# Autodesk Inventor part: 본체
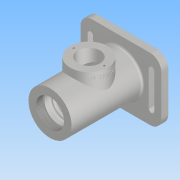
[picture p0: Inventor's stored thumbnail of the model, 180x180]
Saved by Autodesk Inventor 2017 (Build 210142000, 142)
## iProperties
Part Number: 본체
Material: 알루미늄 6061
Document SubType Name: Modeling
Designer: user
Density: 2.7 g/cm^3
Appearance: 알루미늄 - 평지
Mass: 734.635 g
Surface Area: 649.396 cm^2
Volume: 272.087 cm^3
Author: user
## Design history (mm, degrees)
sketch "스케치1"
  geometry: L1 (-58, -45)-(58, -45); L2 (58, -45)-(58, 45); L3 (58, 45)-(-58, 45); L4 (-58, 45)-(-58, -45); L5 (-58, -45)-(58, 45); L6 (58, -45)-(-58, 45); 1 further point
  constraints: 12 end point, 2 midpoint, 2 parallel, 1 horizontal, 1 perpendicular
  dimensions: "d0" = 116 distance of L3.end L2.end; "d1" = 90 distance of L2.end L1.end
extrude "돌출1" new body sketch "스케치1" distance "d2" = 10; taper "d3" = 0 deg
sketch "스케치2"
  geometry: C1 r 35 at (0, 0); 1 further point
  constraints: 1 centre point, 1 coincident
  dimensions: "d4" = 70 diameter of C1
extrude "돌출2" join sketch "스케치2" distance "d5" = 3; taper "d6" = 0 deg
sketch "스케치3"
  geometry: L1 (31, 112)-(0, 112); L2 (0, 112)-(0, 10); L3 (31, -3)-(31, 112); L4 (45, 10)-(-45, 10) reference; L5 (0, 103)-(24, 103); L6 (24, 103)-(24, 100); L7 (24, 100)-(20, 100); L8 (20, 100)-(20, 91); L9 (20, 91)-(17.5, 91); L10 (17.5, 91)-(17.5, 87.75); L11 (17.5, 87.75)-(18.5, 87.75); L12 (18.5, 87.75)-(18.5, 86); L13 (18.5, 86)-(17.5, 86); L14 (17.5, 86)-(17.5, 75); L15 (17.5, 75)-(26, 75); L16 (26, 75)-(26, 37); L17 (26, 37)-(17.5, 37); L18 (17.5, 37)-(17.5, 26); L19 (17.5, 26)-(16, 26); L20 (16, 26)-(16, 21); L21 (16, 21)-(10, 21); L22 (10, 21)-(10, 18.3); L23 (10, 18.3)-(12.5, 18.3); L24 (12.5, 18.3)-(12.5, 11); L25 (12.5, 11)-(17.5, 11); L26 (0, 112)-(0, 103); L27 (-35, -3)-(35, -3) reference; L28 (17.5, 11)-(22, -3); L29 (22, -3)-(31, -3); L30 (0, 103)-(0, -3); L31 (22, -3)-(0, -3); 3 further points
  constraints: 58 end point, 20 perpendicular, 8 point on line, 3 horizontal, 2 collinear, 2 midpoint, 1 coincident, 1 parallel, 1 vertical alignment
  dimensions: "d8" = 62 diameter of L3 L2; "d9" = 3 distance between parallel lines of L5 L7; "d10" = 12 distance between parallel lines of L7 L1; "d11" = 48 diameter of L6 L2; "d12" = 40 diameter of L8 L2; "d13" = 35 diameter of L10 L2; "d14" = 37 diameter of L12 L2; "d16" = 21 distance between parallel lines of L1 L9; "d21" = 91 distance between parallel lines of L1 L21; "d25" = 35 diameter of L14 L2; "d26" = 52 diameter of L16 L2; "d27" = 32 diameter of L20 L2; "d28" = 25 diameter of L24 L2; "d29" = 20 diameter of L22 L2; "d47" = 3.25 distance of L9.end L10.end; "d48" = 1.75 distance of L11.end L12.end; "d49" = 11 distance of L13.end L14.end; "d50" = 38 distance of L15.end L16.end; "d51" = 11 distance of L17.end L18.end; "d52" = 115 distance from line of L27 L1.start; "d53" = 44 diameter of L28.end L2; "d54" = 14 vertical distance of L28.end L25.end; "d55" = 7.3 distance of L23.end L24.end
revolve "회전1" stored, may be unused: angle "d31" = 90 deg
sketch "스케치4"
  geometry: C1 r 31 at (0, 0) reference; 1 further point
  constraints: 1 coincident
hole "구멍1" sketch "스케치4" at (0, 0) diameter "d32" = 40.376; stored, may be unused: countersink angle "d36" = 90 deg, drill point angle "d38" = 0 deg; dims "d33" = 9, "d34" = 4, "d35" = 2, "d37" = 9
revolve "회전2" stored, may be unused: angle "d56" = 90 deg
sketch "스케치7"
  geometry: L1 (44, 29)-(44, -29); L2 (40, 25)-(40, -25); L3 (48, -25)-(48, 25); C1 r 31 at (0, 0) reference; A1 r 4 centre (44, 25) between (48, 25) and (40, 25); A2 r 4 centre (44, -25) between (40, -25) and (48, -25); 1 further point
  constraints: 8 end point, 6 point on circle, 4 tangent, 2 centre point, 2 point on line, 1 horizontal alignment, 1 midpoint, 1 parallel, 1 vertical
  dimensions: "d57" = 4 radius of A1; "d58" = 50 distance of A2.centre A1.centre; "d59" = 44 distance of C1.centre point (44, 0)
extrude "돌출5" cut sketch "스케치7" distance "d60" = 50; taper "d61" = 0 deg
fillet "모깎기1" dims "d70" = 3
fillet "모깎기2" dims "d71" = 0.3
fillet "모깎기3" dims "d72" = 3
chamfer "모따기1" distance "d73" = 0.7; stored, may be unused: second distance "d74" = 2, angle "d75" = 30 deg
chamfer "모따기3" distance "d79" = 1; stored, may be unused: second distance "d80" = 2, angle "d81" = 30 deg
fillet "모깎기4" dims "d82" = 16
node "작업 평면1"
fillet "모깎기5" dims "d87" = 3
node "작업 평면2"
sketch "스케치10"
  geometry: L1 (-42, 10)-(42, 10) reference; L2 (-42, 0)-(42, 0) reference; C1 r 27 at (0, 56); 2 further points
  constraints: 1 centre point, 1 midpoint, 1 vertical alignment
  dimensions: "d89" = 54 diameter of C1; "d90" = 46 distance from line of L1 C1.centre
extrude "돌출6" join sketch "스케치10" stored distance "d91" = 50; taper "d92" = 0 deg
sketch "스케치11"
  geometry: C1 r 27 at (0, 0) reference; C2 r 16 at (0, 0); 1 further point
  constraints: 1 centre point, 1 coincident
  dimensions: "d93" = 32 diameter of C2
extrude "돌출7" cut sketch "스케치11" distance "d94" = 45; taper "d95" = 0 deg
sketch "스케치12"
  geometry: C1 r 16 at (0, 0) reference; C2 r 27 at (0, 0) reference; A1 r 22 centre (0, 0) between (-22, 0) and (22, 0); 1 further point
  constraints: 2 horizontal alignment, 2 point on circle, 1 centre point, 1 coincident
  dimensions: "d96" = 44 diameter of A1
hole "구멍3" sketch "스케치12" at (-22, 0), (22, 0) diameter "d97" = 2.459; stored, may be unused: countersink angle "d101" = 90 deg, drill point angle "d103" = 118 deg; dims "d98" = 6, "d99" = 4, "d100" = 2, "d102" = 8
sketch "스케치13"
  geometry: L1 (42, 83)-(42, 29) reference; 3 further points
  constraints: 1 horizontal alignment, 1 midpoint, 1 other
  dimensions: "d104" = 8 distance from line of L1 point (34, 56)
feature "엠보싱2" sketch "스케치13" dims "d0" = 116, "d1" = 90, "d105" = 0.5, "d106" = 0
node "솔리드1"
mirror "미러1"
other parameters: "d88" = 42
